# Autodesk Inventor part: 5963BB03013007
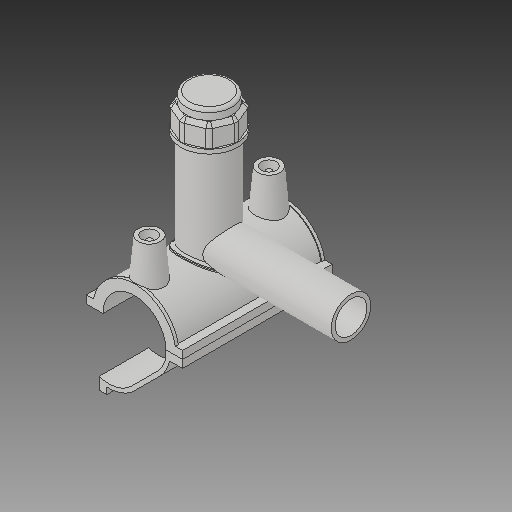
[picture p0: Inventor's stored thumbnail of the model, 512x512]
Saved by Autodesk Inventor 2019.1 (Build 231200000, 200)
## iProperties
Created: 2017-07
Part Number: 5963BB03013007
Material: Generic
Description: PLASSON TAPPING SADDLE 1 1/4''IPS x 3/4''IPS
Document SubType Name: Modeling
Designer: KIM
Mass: 1712.7 g
Surface Area: 2671.49 cm^2
Volume: 1712.7 cm^3
Density: 1 g/cm^3
Appearance: Default
Author: KIM
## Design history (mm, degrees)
derived "5963B.ipt"
feature "Solid1::5963B.ipt"
feature "Solid2::5963B.ipt"
feature "Solid4::5963B.ipt"
feature "Solid5::5963B.ipt"
tag "TaggingFeature1"
body "Solid1"
body "Solid2"
other parameters: "d_" = 42.1, "B_" = 64.516, "L_" = 100.076, "d_t" = 6, "H_2" = 93.726, "H_1" = 9.906, "d_1" = 26.6, "H_" = 94.996, "d1" = 54.73, "d148" = 0.6315, "d160" = 0.6315, "d169" = 3.2805, "d192" = 6.1236, "d0" = 42.1, "d2" = 64.516, "d3" = 10.525, "d4" = 100.076, "d5" = 0, "d6" = 0.1, "d8" = 0, "d19" = 6, "d20" = 6, "d21" = 60.0456, "d23" = 0, "d24" = 30.0228, "d26" = 0, "d29" = 3, "d30" = 14.03333, "d31" = 6, "d32" = 0, "d33" = 0, "d34" = 0.6, "d40" = 28.4596, "d41" = 37.89, "d43" = 0, "d45" = 0, "d47" = 87.4106, "d70" = 15, "d72" = 0, "d73" = 6, "d75" = 5, "d76" = 0, "d77" = 2.105, "d78" = 51.05, "d79" = 15, "d80" = 40.0304, "d82" = 5 deg, "d84" = 4, "d85" = 14, "d86" = 0, "d87" = 3, "d88" = 0, "d89" = 1, "d90" = 1, "d91" = 80.0608, "d92" = 0, "d93" = 0.5, "d94" = 22.15789, "d96" = 55.8246, "d97" = 2.00152, "d98" = 0, "d102" = 0.421, "d120" = 140 deg, "d121" = 24.228, "d122" = 20 deg, "d123" = 109.46, "d124" = 32.838, "d126" = 0, "d143" = 43.363, "d145" = 9.71538, "d149" = 0.6315, "d150" = 10.68692, "d153" = 100.076, "d154" = 0, "d156" = 27.365, "d157" = 160 deg, "d159" = 2.526, "d161" = 0.6315, "d162" = 60.0456, "d163" = 0, "d164" = 21.05, "d167" = 4.21, "d168" = 26.69756, "d170" = 3.2805, "d172" = 0, "d173" = 1, "d175" = 21.05, "d176" = 20 deg, "d177" = 2.947, "d178" = 12.63, "d180" = 0, "d183" = 5.052, "d184" = 2.3576, "d185" = 32.5247, "d186" = 32.5247, "d187" = 27.365, "d188" = 3.789, "d189" = 2.947, "d190" = 0, "d191" = 41.0475, "d193" = 6.1236, "d194" = 3.50266, "d195" = 90 deg, "d197" = 0, "d199" = 0, "d200" = 6.315, "d202" = 0, "d203" = 93.726, "d204" = 35.9955, "d205" = 26.523, "d206" = 32.2065, "d207" = 70.2945, "d208" = 73.10628, "d209" = 87.16518, "d210" = 32.5854, "d211" = 37.89, "d212" = 30.312, "d213" = -3.0546, "d216" = 0, "d217" = 4.21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
